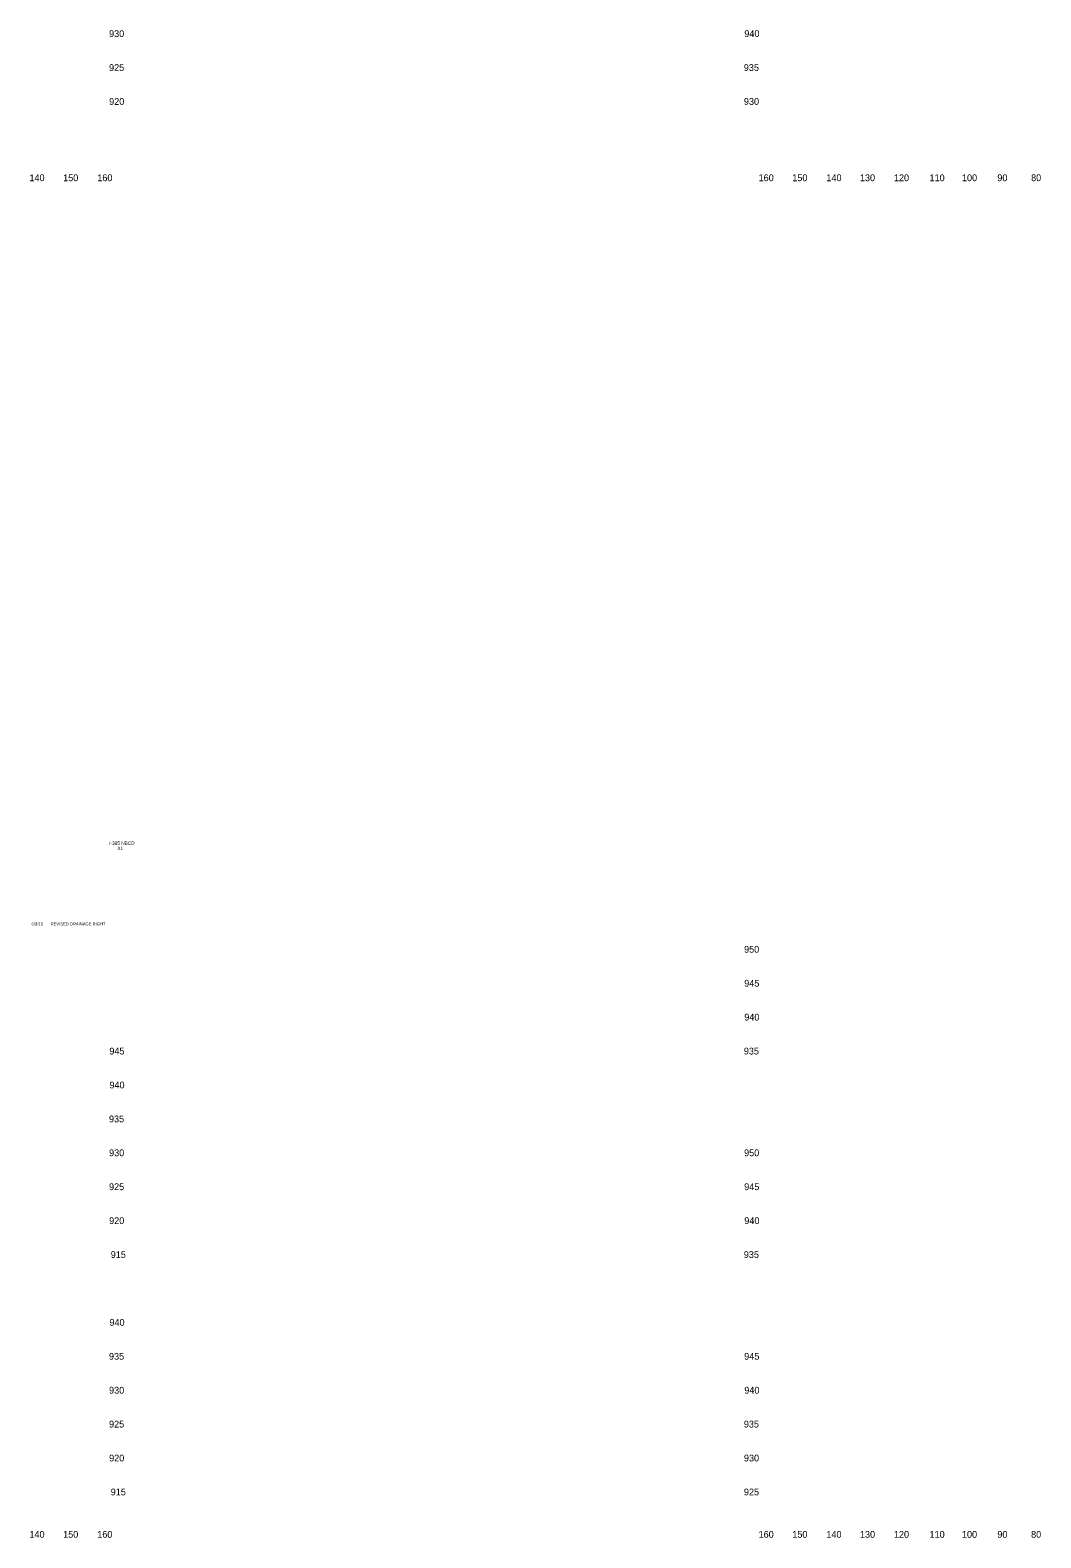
# Model space of a CAD drawing. Extents: x 4994 to 7391, y 4997 to 8804.
# Drawn here: x 5298.3 to 5596.3, y 4997.5 to 5442 of the extents above; entities that cross this region are included whole.
import ezdxf

# ---------------------------------------------------------------- set-up
doc = ezdxf.new("R2010")
doc.units = 0
for name, color, linetype in [('RD_SHT_ID', 7, 'Continuous'), ('RD_SHT_TX', 7, 'Continuous'), ('RD_XS_TX_Offset', 7, 'Continuous')]:
    doc.layers.add(name, color=color, linetype=linetype)

msp = doc.modelspace()

# ---------------------------------------------------------------- texts
at = {"layer": 'RD_SHT_ID'}
for s, p in [('I-385 NBCD', (5321.64, 5201.8)), ('X1', (5324.02, 5200.3))]:
    msp.add_text(s, height=1, dxfattribs=at).set_placement(p)
at = {"layer": 'RD_SHT_TX'}
for s, p in [('6/3/16', (5298.71, 5178.05)), ('REVISED DRAINAGE RIGHT', (5304.35, 5178.05))]:
    msp.add_text(s, height=0.88, dxfattribs=at).set_placement(p)
at = {"layer": 'RD_XS_TX_Offset'}
for s, p in [('930', (5321.58, 5440)), ('940', (5508.89, 5440)), ('925', (5321.57, 5430)), ('935', (5508.75, 5430)), ('920', (5321.6, 5420)), ('930', (5508.78, 5420)), ('140', (5298.1, 5397.5)), ('150', (5308.04, 5397.5)), ('160', (5318.1, 5397.5)), ('160', (5513.1, 5397.5)), ('150', (5523.04, 5397.5)), ('140', (5533.1, 5397.5)), ('130', (5542.99, 5397.5)), ('120', (5553.01, 5397.5)), ('110', (5563.51, 5397.5)), ('100', (5573.07, 5397.5)), ('90', (5583.5, 5397.5)), ('80', (5593.46, 5397.5)), ('950', (5508.83, 5170)), ('945', (5508.86, 5160)), ('940', (5508.89, 5150)), ('945', (5321.66, 5140)), ('935', (5508.75, 5140)), ('940', (5321.69, 5130)), ('935', (5321.55, 5120)), ('930', (5321.58, 5110)), ('950', (5508.83, 5110)), ('925', (5321.57, 5100)), ('945', (5508.86, 5100)), ('920', (5321.6, 5090)), ('940', (5508.89, 5090)), ('915', (5322.07, 5080)), ('935', (5508.75, 5080)), ('940', (5321.69, 5060)), ('935', (5321.55, 5050)), ('945', (5508.86, 5050)), ('930', (5321.58, 5040)), ('940', (5508.89, 5040)), ('925', (5321.57, 5030)), ('935', (5508.75, 5030)), ('920', (5321.6, 5020)), ('930', (5508.78, 5020)), ('915', (5322.07, 5010)), ('925', (5508.77, 5010)), ('140', (5298.1, 4997.5)), ('150', (5308.04, 4997.5)), ('160', (5318.1, 4997.5)), ('160', (5513.1, 4997.5)), ('150', (5523.04, 4997.5)), ('140', (5533.1, 4997.5)), ('130', (5542.99, 4997.5)), ('120', (5553.01, 4997.5)), ('110', (5563.51, 4997.5)), ('100', (5573.07, 4997.5)), ('90', (5583.5, 4997.5)), ('80', (5593.46, 4997.5))]:
    msp.add_text(s, height=2, dxfattribs=at).set_placement(p)

doc.saveas('drawing.dxf')
